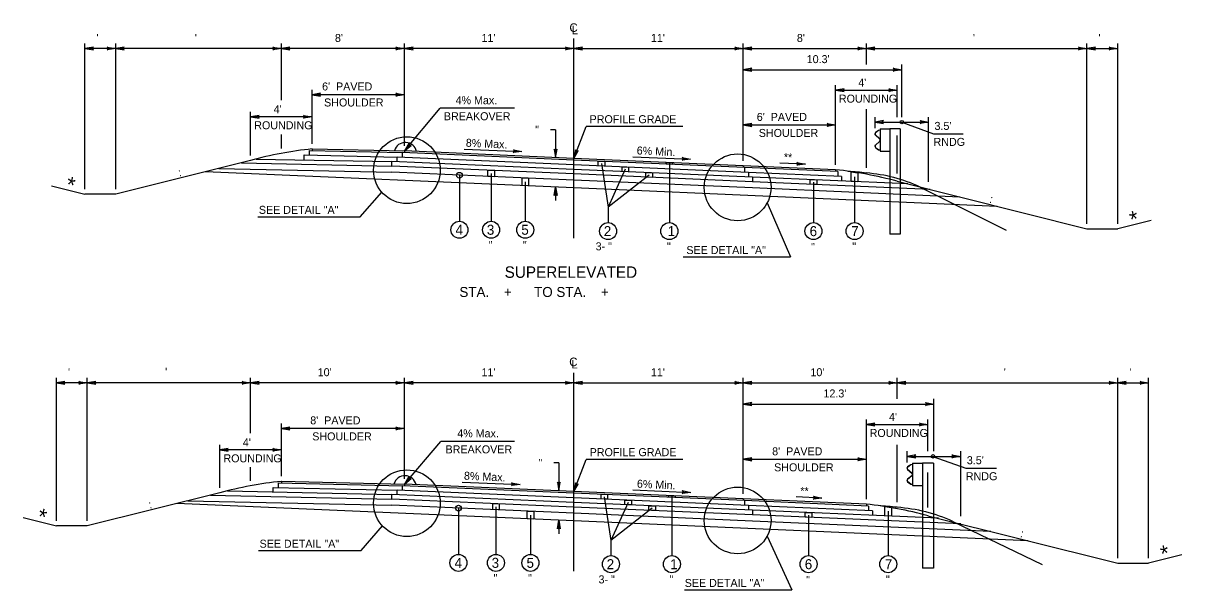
# Model space of a CAD drawing. Extents: x -592 to 1199, y -590 to 416.
# Drawn here: x 716.2 to 918.9, y -324.2 to -225.1 of the extents above; entities that cross this region are included whole.
import ezdxf

# ---------------------------------------------------------------- set-up
doc = ezdxf.new("R2010")
doc.units = 0
doc.layers.add('1', color=7, linetype='Continuous')
doc.layers.add('Des_ Drain_ Ftrs', color=7, linetype='Continuous')

msp = doc.modelspace()

# ---------------------------------------------------------------- linework, layer by layer
at = {"layer": '1'}
for p, q in [((726.98, -254.1), (726.98, -228.63)), ((732.37, -254.1), (732.37, -228.63)), ((761.34, -238.52), (761.34, -228.63)), ((782.89, -246.54), (782.89, -228.63)), ((812.53, -262.69), (812.53, -227.75)), ((842.16, -249.13), (842.16, -228.63)), ((863.71, -232.33), (863.71, -228.63)), ((902.31, -260.15), (902.31, -228.63)), ((907.69, -260.15), (907.69, -228.63)), ((732.37, -229.51), (726.98, -229.51)), ((761.34, -229.51), (732.37, -229.51)), ((782.89, -229.51), (761.34, -229.51)), ((812.53, -229.51), (782.89, -229.51)), ((812.53, -229.51), (842.16, -229.51)), ((842.16, -229.51), (863.71, -229.51)), ((863.71, -229.51), (902.31, -229.51)), ((902.31, -229.51), (907.69, -229.51)), ((869.91, -241.49), (869.91, -232.33)), ((842.16, -233.21), (869.91, -233.21)), ((766.73, -246.19), (766.73, -236.71)), ((858.33, -249.84), (858.33, -235.9)), ((858.33, -236.78), (869.1, -236.78)), ((869.1, -241.49), (869.1, -235.9)), ((782.89, -237.59), (766.73, -237.59)), ((755.95, -248.2), (755.95, -240.57)), ((782.88, -247.42), (789.14, -239.95)), ((802.11, -239.95), (789.14, -239.95)), ((863.71, -250.4), (863.71, -240.14)), ((766.73, -241.45), (755.95, -241.45)), ((812.53, -248.72), (814.67, -243.15)), ((831.59, -243.15), (814.67, -243.15)), ((842.16, -242.87), (858.33, -242.87)), ((865.22, -243.44), (865.22, -241.49)), ((865.22, -242.37), (874.6, -242.37)), ((869.91, -242.37), (875.47, -244.44)), ((874.6, -252.85), (874.6, -241.49)), ((761.34, -246.97), (761.34, -244.52)), ((809.33, -243.7), (808.45, -243.7)), ((809.33, -243.7), (809.33, -248.58)), ((865.28, -244.66), (866.01, -245.29)), ((865.82, -243.83), (865.3, -244.22)), ((865.3, -244.63), (866.03, -245.27)), ((865.83, -243.86), (865.32, -244.25)), ((866.13, -243.78), (865.82, -243.83)), ((866.13, -243.81), (865.83, -243.86)), ((866.13, -243.55), (866.13, -247.48)), ((866.13, -243.55), (867.82, -243.55)), ((867.82, -243.55), (867.82, -261.95)), ((869.64, -243.55), (867.82, -243.55)), ((869.1, -251.36), (869.1, -244.72)), ((869.64, -243.55), (869.64, -261.95)), ((875.47, -244.44), (880.62, -244.44)), ((766.73, -247.07), (782.88, -247.42)), ((766.73, -247.07), (766.73, -247.37)), ((793.31, -247.08), (803.42, -247.52)), ((866.01, -245.74), (865.28, -246.38)), ((866.03, -245.76), (865.3, -246.4)), ((865.3, -246.81), (865.82, -247.2)), ((865.32, -246.79), (865.83, -247.17)), ((865.82, -247.2), (866.13, -247.25)), ((865.83, -247.17), (866.13, -247.22)), ((866.1, -245.48), (866.1, -245.55)), ((866.13, -245.48), (866.13, -245.55)), ((755.95, -249.08), (732.37, -254.98)), ((756.91, -248.83), (780.7, -249.25)), ((765.34, -248.12), (781.62, -248.48)), ((765.34, -248.98), (765.34, -248.12)), ((766.27, -247.36), (782.54, -247.71)), ((766.27, -248.14), (766.27, -247.36)), ((812.53, -250.64), (780.7, -249.25)), ((780.7, -250.06), (780.7, -249.25)), ((812.53, -249.83), (781.62, -248.48)), ((781.62, -249.29), (781.62, -248.48)), ((812.53, -249.02), (782.54, -247.71)), ((782.54, -248.52), (782.54, -247.71)), ((812.53, -248.72), (782.88, -247.42)), ((782.88, -247.42), (782.88, -247.72)), ((842.17, -250.01), (812.53, -248.72)), ((842.4, -250.32), (812.53, -249.02)), ((822.83, -248.42), (832.94, -248.86)), ((866.13, -247.48), (867.82, -247.48)), ((812.53, -253.87), (748.05, -251.06)), ((750.39, -250.47), (780.7, -251.14)), ((754.35, -249.48), (780.7, -250.06)), ((812.53, -251.45), (780.7, -250.06)), ((812.53, -252.52), (780.7, -251.14)), ((798.05, -251.38), (798.05, -259.72)), ((843.1, -251.16), (812.53, -249.83)), ((843.81, -252), (812.53, -250.64)), ((817.35, -249.63), (818.51, -257.26)), ((821.52, -250.62), (818.51, -257.26)), ((829.23, -249.62), (829.23, -259.96)), ((858.33, -250.72), (842.17, -250.01)), ((842.17, -250.01), (842.17, -250.31)), ((858.69, -251.03), (842.4, -250.32)), ((842.4, -250.32), (842.4, -251.13)), ((859.38, -251.87), (843.1, -251.16)), ((843.1, -251.16), (843.1, -251.97)), ((853.03, -249.74), (848.54, -249.55)), ((858.33, -250.72), (858.33, -251.02)), ((858.69, -251.03), (858.69, -251.84)), ((792.5, -251.67), (792.5, -259.72)), ((804.02, -252.8), (804.02, -259.72)), ((843.81, -252.81), (812.53, -251.45)), ((843.81, -253.89), (812.53, -252.52)), ((825.7, -251.63), (818.51, -257.26)), ((843.81, -252), (843.81, -252.81)), ((870.94, -253.19), (843.81, -252)), ((874.86, -254.17), (843.81, -252.81)), ((854.45, -252.89), (854.45, -259.96)), ((859.38, -251.87), (859.38, -252.68)), ((861.65, -251.94), (861.65, -259.96)), ((865.22, -251.5), (865.22, -251.5)), ((869.1, -252.73), (902.3, -261.03)), ((721.15, -253.52), (726.98, -254.98)), ((732.37, -254.98), (726.98, -254.98)), ((775.16, -258.92), (778.9, -254.6)), ((809.33, -253.73), (809.33, -256.1)), ((886.62, -257.11), (812.53, -253.87)), ((880.08, -255.48), (843.81, -253.89)), ((873.1, -253.73), (888.15, -261.26)), ((818.51, -257.26), (818.51, -259.96)), ((846.36, -256.49), (850.42, -265.95)), ((757.22, -258.92), (775.16, -258.92)), ((902.3, -261.03), (907.69, -261.03)), ((913.52, -259.57), (907.69, -261.03)), ((869.64, -261.95), (867.82, -261.95)), ((831.63, -265.95), (850.42, -265.95)), ((721.99, -312.13), (721.99, -287.1)), ((727.38, -312.13), (727.38, -287.1)), ((755.95, -296.8), (755.95, -287.1)), ((782.89, -304.79), (782.89, -287.1)), ((812.53, -320.94), (812.53, -286.22)), ((842.16, -307.38), (842.16, -287.1)), ((869.1, -290.8), (869.1, -287.1)), ((907.69, -318.63), (907.69, -287.1)), ((913.08, -318.63), (913.08, -287.1)), ((727.38, -287.98), (721.99, -287.98)), ((755.95, -287.98), (727.38, -287.98)), ((782.89, -287.98), (755.95, -287.98)), ((812.53, -287.98), (782.89, -287.98)), ((812.53, -287.98), (842.16, -287.98)), ((842.16, -287.98), (869.1, -287.98)), ((869.1, -287.98), (907.69, -287.98)), ((907.69, -287.98), (913.08, -287.98)), ((842.16, -291.68), (875.53, -291.68)), ((875.53, -299.95), (875.53, -290.8)), ((761.34, -304.32), (761.34, -295.06)), ((782.89, -295.94), (761.34, -295.94)), ((863.71, -308.32), (863.71, -294.37)), ((863.71, -295.25), (874.49, -295.25)), ((874.49, -299.95), (874.49, -294.37)), ((750.56, -306.33), (750.56, -298.81)), ((761.34, -299.69), (750.56, -299.69)), ((782.88, -305.67), (789.22, -298.21)), ((802.15, -298.21), (789.22, -298.21)), ((869.1, -308.86), (869.1, -298.82)), ((870.84, -301.9), (870.84, -299.95)), ((880.22, -311.32), (880.22, -299.95)), ((809.9, -301.97), (809.02, -301.97)), ((809.9, -301.97), (809.9, -306.85)), ((812.53, -306.97), (814.68, -301.38)), ((831.6, -301.38), (814.68, -301.38)), ((842.16, -301.35), (863.71, -301.35)), ((870.84, -300.83), (880.22, -300.83)), ((871.79, -302.02), (871.79, -305.95)), ((871.79, -302.02), (873.53, -302.02)), ((873.53, -302.02), (873.53, -320.41)), ((875.43, -302.02), (873.53, -302.02)), ((875.36, -300.83), (881.12, -302.91)), ((875.43, -302.02), (875.43, -320.41)), ((755.95, -305.1), (755.95, -302.75)), ((870.91, -303.12), (871.67, -303.76)), ((871.46, -302.3), (870.92, -302.69)), ((870.93, -303.1), (871.69, -303.74)), ((871.47, -302.33), (870.94, -302.71)), ((871.79, -302.25), (871.46, -302.3)), ((871.79, -302.28), (871.47, -302.33)), ((871.76, -303.95), (871.76, -304.02)), ((871.79, -303.95), (871.79, -304.02)), ((874.49, -309.78), (874.49, -303.63)), ((881.12, -302.91), (886.47, -302.91)), ((760.85, -305.49), (782.54, -305.96)), ((760.85, -306.27), (760.85, -305.49)), ((761.34, -305.2), (782.88, -305.67)), ((761.34, -305.2), (761.34, -305.5)), ((812.53, -307.27), (782.54, -305.96)), ((782.54, -306.77), (782.54, -305.96)), ((812.53, -306.97), (782.88, -305.67)), ((782.88, -305.67), (782.88, -305.97)), ((792.99, -305.32), (803.1, -305.76)), ((871.67, -304.21), (870.91, -304.84)), ((870.92, -305.28), (871.46, -305.67)), ((871.69, -304.23), (870.93, -304.87)), ((870.94, -305.25), (871.47, -305.64)), ((871.46, -305.67), (871.79, -305.72)), ((871.47, -305.64), (871.79, -305.69)), ((871.79, -305.95), (873.53, -305.95)), ((750.56, -307.21), (727.38, -313.01)), ((748.97, -307.61), (780.7, -308.31)), ((751.89, -306.87), (780.7, -307.5)), ((759.92, -306.25), (781.62, -306.73)), ((759.92, -307.04), (759.92, -306.25)), ((812.53, -308.89), (780.7, -307.5)), ((780.7, -308.31), (780.7, -307.5)), ((812.53, -308.08), (781.62, -306.73)), ((781.62, -307.54), (781.62, -306.73)), ((842.17, -308.26), (812.53, -306.97)), ((842.4, -308.57), (812.53, -307.27)), ((843.1, -309.41), (812.53, -308.08)), ((817.85, -307.9), (819.02, -315.52)), ((822.86, -306.7), (832.98, -307.14)), ((829.68, -307.88), (829.68, -318.21)), ((855.92, -308.12), (851.43, -307.92)), ((812.53, -312.12), (743.06, -309.09)), ((745, -308.6), (780.7, -309.38)), ((812.53, -309.69), (780.7, -308.31)), ((812.53, -310.77), (780.7, -309.38)), ((792.33, -309.89), (792.33, -317.97)), ((798.89, -309.64), (798.89, -317.97)), ((843.81, -310.25), (812.53, -308.89)), ((843.81, -311.06), (812.53, -309.69)), ((822.03, -308.88), (819.02, -315.52)), ((826.2, -309.89), (819.02, -315.52)), ((863.71, -309.2), (842.17, -308.26)), ((842.17, -308.26), (842.17, -308.56)), ((864.1, -309.52), (842.4, -308.57)), ((842.4, -308.57), (842.4, -309.38)), ((864.8, -310.36), (843.1, -309.41)), ((843.1, -309.41), (843.1, -310.22)), ((863.71, -309.2), (863.71, -309.5)), ((864.1, -309.52), (864.1, -310.33)), ((870.84, -309.96), (870.84, -309.96)), ((716.16, -311.55), (721.99, -313.01)), ((804.93, -311.11), (804.93, -317.97)), ((809.9, -312), (809.9, -314.37)), ((843.81, -312.14), (812.53, -310.77)), ((892.01, -315.59), (812.53, -312.12)), ((843.81, -310.25), (843.81, -311.06)), ((876.32, -311.67), (843.81, -310.25)), ((880.24, -312.65), (843.81, -311.06)), ((885.47, -313.96), (843.81, -312.14)), ((853.6, -311.1), (853.6, -318.21)), ((864.8, -310.36), (864.8, -311.17)), ((867.53, -310.42), (867.53, -318.21)), ((874.49, -311.21), (907.69, -319.51)), ((878.84, -312.2), (894.46, -319.72)), ((727.38, -313.01), (721.99, -313.01)), ((775.28, -317.31), (779.02, -312.99)), ((819.02, -315.52), (819.02, -318.21)), ((846.34, -314.78), (850.69, -324.17)), ((757.35, -317.31), (775.28, -317.31)), ((918.9, -318.06), (913.08, -319.51)), ((907.69, -319.51), (913.08, -319.51)), ((875.43, -320.41), (873.53, -320.41)), ((831.91, -324.17), (850.69, -324.17))]:
    msp.add_line(p, q, dxfattribs=at)
for points in [[(816.77, -249.2), (817.92, -249.25), (817.92, -250.06), (816.77, -250.01)], [(797.48, -250.79), (798.63, -250.84), (798.63, -251.92), (797.48, -251.87)], [(820.95, -250.2), (822.1, -250.25), (822.1, -251.06), (820.95, -251.01)], [(825.12, -251.19), (826.27, -251.24), (826.27, -252.05), (825.12, -252)], [(828.66, -249.42), (829.8, -249.47), (829.8, -249.77), (828.66, -249.72)], [(861.07, -251.06), (862.22, -251.24), (862.22, -252.81), (861.07, -252.76)], [(803.45, -252.13), (804.6, -252.18), (804.6, -253.53), (803.45, -253.48)], [(853.88, -252.44), (855.02, -252.49), (855.02, -253.3), (853.88, -253.25)], [(817.28, -307.47), (818.43, -307.52), (818.43, -308.33), (817.28, -308.28)], [(829.1, -307.69), (830.25, -307.74), (830.25, -308.04), (829.1, -307.99)], [(798.32, -309.07), (799.47, -309.12), (799.47, -310.2), (798.32, -310.15)], [(821.45, -308.47), (822.6, -308.52), (822.6, -309.33), (821.45, -309.28)], [(825.63, -309.46), (826.78, -309.51), (826.78, -310.32), (825.63, -310.27)], [(866.96, -309.62), (868.11, -309.8), (868.11, -311.31), (866.96, -311.26)], [(804.36, -310.42), (805.5, -310.47), (805.5, -311.81), (804.36, -311.76)], [(853.02, -310.65), (854.17, -310.7), (854.17, -311.51), (853.02, -311.46)]]:
    msp.add_lwpolyline(points, close=True, dxfattribs=at)
for centre, radius in [((869.91, -242.37), 0.3), ((783.31, -250.78), 5.84), ((841.18, -253.79), 5.84), ((792.5, -251.67), 0.5), ((792.5, -261.21), 1.49), ((798.05, -261.21), 1.49), ((804.02, -261.21), 1.49), ((818.51, -261.44), 1.49), ((829.23, -261.44), 1.49), ((854.45, -261.44), 1.49), ((861.65, -261.44), 1.49), ((783.31, -309.03), 5.84), ((841.18, -312.04), 5.84), ((792.33, -309.89), 0.5), ((792.33, -319.46), 1.49), ((798.89, -319.46), 1.49), ((804.93, -319.46), 1.49), ((819.02, -319.69), 1.49), ((829.68, -319.69), 1.49), ((853.6, -319.69), 1.49), ((867.53, -319.69), 1.49)]:
    msp.add_circle(centre, radius, dxfattribs=at)
for centre, radius, start, end in [((865.47, -244.45), 0.278, 126.9799, 229.021), ((865.47, -244.45), 0.249, 126.9799, 229.021), ((865.85, -245.48), 0.249, 0, 49.0365), ((865.85, -245.48), 0.278, 0, 49.0365), ((773.62, -313.9), 67.19, 95.8897, 105.2483), ((783.04, -247.94), 2, 12.248, 163.8505), ((865.47, -246.59), 0.278, 130.979, 233.0201), ((865.47, -246.59), 0.249, 130.979, 233.0201), ((865.85, -245.55), 0.249, 310.9635, 0), ((865.85, -245.55), 0.278, 310.9635, 0), ((851.44, -317.55), 67.19, 74.7602, 84.1188), ((852.89, -351.94), 101.24, 83.8633, 85.6775), ((861.59, -278.56), 27.37, 65.1374, 85.5513), ((768.23, -372.04), 67.19, 95.8911, 105.2497), ((782.96, -306.21), 2, 12.9578, 163.1849), ((856.83, -376.04), 67.19, 74.7602, 84.1188)]:
    msp.add_arc(centre, radius, start, end, dxfattribs=at)
msp.add_ellipse((875.36, -300.83), major_axis=(-0.311, 0), ratio=0.964041, dxfattribs=at)
for centre, major_axis, start_param, end_param in [((871.1, -302.91), (-0.288, 0), 5.35781, 7.138763), ((871.1, -302.91), (-0.258, 0), 5.35781, 7.138763), ((871.5, -303.95), (0.258, 0), 0, 0.855848), ((871.5, -304.02), (0.258, 0), 5.427337, 6.283185), ((871.5, -303.95), (0.288, 0), 0, 0.855848), ((871.5, -304.02), (0.288, 0), 5.427337, 6.283185), ((871.1, -305.05), (-0.288, 0), 5.427608, 7.208561), ((871.1, -305.05), (-0.258, 0), 5.427608, 7.208561), ((857.88, -410.41), (105.02, 0), 1.463691, 1.495354), ((866.91, -337.03), (28.39, 0), 1.136862, 1.493152)]:
    msp.add_ellipse(centre, major_axis=major_axis, ratio=0.964041, start_param=start_param, end_param=end_param, dxfattribs=at)
at = {"layer": 'Des_ Drain_ Ftrs'}
for points in [[(726.98, -229.51), (728.47, -229.76), (728.17, -229.51), (728.47, -229.26)], [(732.37, -229.51), (730.88, -229.76), (731.17, -229.51), (730.88, -229.26)], [(732.37, -229.51), (733.86, -229.76), (733.56, -229.51), (733.86, -229.26)], [(761.34, -229.51), (759.85, -229.76), (760.14, -229.51), (759.85, -229.26)], [(761.34, -229.51), (762.83, -229.76), (762.53, -229.51), (762.83, -229.26)], [(782.89, -229.51), (781.4, -229.76), (781.7, -229.51), (781.4, -229.26)], [(782.89, -229.51), (784.38, -229.76), (784.08, -229.51), (784.38, -229.26)], [(812.53, -229.51), (811.04, -229.76), (811.33, -229.51), (811.04, -229.26)], [(812.53, -229.51), (814.01, -229.76), (813.72, -229.51), (814.01, -229.26)], [(842.16, -229.51), (840.67, -229.76), (840.97, -229.51), (840.67, -229.26)], [(842.16, -229.51), (843.65, -229.76), (843.35, -229.51), (843.65, -229.26)], [(863.71, -229.51), (862.23, -229.76), (862.52, -229.51), (862.23, -229.26)], [(863.71, -229.51), (865.2, -229.76), (864.91, -229.51), (865.2, -229.26)], [(902.31, -229.51), (900.82, -229.76), (901.11, -229.51), (900.82, -229.26)], [(902.31, -229.51), (903.79, -229.76), (903.5, -229.51), (903.79, -229.26)], [(907.69, -229.51), (906.21, -229.76), (906.5, -229.51), (906.21, -229.26)], [(842.16, -233.21), (843.65, -233.46), (843.35, -233.21), (843.65, -232.96)], [(869.91, -233.21), (868.42, -233.46), (868.72, -233.21), (868.42, -232.96)], [(858.33, -236.78), (859.81, -237.03), (859.52, -236.78), (859.81, -236.54)], [(869.1, -236.78), (867.61, -237.03), (867.91, -236.78), (867.61, -236.54)], [(766.73, -237.59), (768.21, -237.83), (767.92, -237.59), (768.21, -237.34)], [(782.89, -237.59), (781.4, -237.83), (781.7, -237.59), (781.4, -237.34)], [(755.95, -241.45), (757.44, -241.7), (757.14, -241.45), (757.44, -241.2)], [(766.73, -241.45), (765.24, -241.7), (765.53, -241.45), (765.24, -241.2)], [(842.16, -242.87), (843.65, -243.12), (843.35, -242.87), (843.65, -242.62)], [(858.33, -242.87), (856.84, -243.12), (857.13, -242.87), (856.84, -242.62)], [(865.22, -242.37), (866.71, -242.61), (866.41, -242.37), (866.71, -242.12)], [(874.6, -242.37), (873.11, -242.61), (873.41, -242.37), (873.11, -242.12)], [(782.88, -247.42), (784.03, -246.44), (783.65, -246.51), (783.65, -246.12)], [(803.42, -247.52), (801.92, -247.71), (802.23, -247.47), (801.95, -247.21)], [(809.33, -248.58), (809.58, -247.09), (809.33, -247.39), (809.08, -247.09)], [(812.53, -248.72), (813.29, -247.42), (812.95, -247.6), (812.83, -247.24)], [(832.94, -248.86), (831.45, -249.05), (831.75, -248.81), (831.47, -248.55)], [(853.03, -249.74), (851.54, -249.93), (851.84, -249.69), (851.56, -249.43)], [(809.33, -253.73), (809.58, -255.22), (809.33, -254.93), (809.08, -255.22)], [(721.99, -287.98), (723.48, -288.22), (723.19, -287.98), (723.48, -287.73)], [(727.38, -287.98), (725.89, -288.22), (726.19, -287.98), (725.89, -287.73)], [(727.38, -287.98), (728.87, -288.22), (728.57, -287.98), (728.87, -287.73)], [(755.95, -287.98), (754.46, -288.22), (754.76, -287.98), (754.46, -287.73)], [(755.95, -287.98), (757.44, -288.22), (757.14, -287.98), (757.44, -287.73)], [(782.89, -287.98), (781.4, -288.22), (781.7, -287.98), (781.4, -287.73)], [(782.89, -287.98), (784.38, -288.22), (784.08, -287.98), (784.38, -287.73)], [(812.53, -287.98), (811.04, -288.22), (811.33, -287.98), (811.04, -287.73)], [(812.53, -287.98), (814.01, -288.22), (813.72, -287.98), (814.01, -287.73)], [(842.16, -287.98), (840.67, -288.22), (840.97, -287.98), (840.67, -287.73)], [(842.16, -287.98), (843.65, -288.22), (843.35, -287.98), (843.65, -287.73)], [(869.1, -287.98), (867.61, -288.22), (867.91, -287.98), (867.61, -287.73)], [(869.1, -287.98), (870.59, -288.22), (870.3, -287.98), (870.59, -287.73)], [(907.69, -287.98), (906.2, -288.22), (906.5, -287.98), (906.2, -287.73)], [(907.69, -287.98), (909.18, -288.22), (908.88, -287.98), (909.18, -287.73)], [(913.08, -287.98), (911.59, -288.22), (911.88, -287.98), (911.59, -287.73)], [(842.16, -291.68), (843.65, -291.93), (843.36, -291.68), (843.65, -291.43)], [(875.53, -291.68), (874.04, -291.93), (874.34, -291.68), (874.04, -291.43)], [(761.34, -295.94), (762.83, -296.19), (762.53, -295.94), (762.83, -295.7)], [(782.89, -295.94), (781.4, -296.19), (781.7, -295.94), (781.4, -295.7)], [(863.71, -295.25), (865.2, -295.5), (864.91, -295.25), (865.2, -295)], [(874.49, -295.25), (873, -295.5), (873.3, -295.25), (873, -295)], [(750.56, -299.69), (752.05, -299.94), (751.75, -299.69), (752.05, -299.44)], [(761.34, -299.69), (759.85, -299.94), (760.14, -299.69), (759.85, -299.44)], [(842.16, -301.35), (843.65, -301.6), (843.35, -301.35), (843.65, -301.1)], [(863.71, -301.35), (862.23, -301.6), (862.52, -301.35), (862.23, -301.1)], [(870.84, -300.83), (872.38, -301.08), (872.08, -300.83), (872.38, -300.59)], [(880.22, -300.83), (878.68, -301.08), (878.99, -300.83), (878.68, -300.59)], [(782.88, -305.67), (784.04, -304.7), (783.66, -304.76), (783.66, -304.38)], [(803.1, -305.76), (801.6, -305.94), (801.91, -305.71), (801.63, -305.45)], [(809.9, -306.85), (810.15, -305.36), (809.9, -305.66), (809.65, -305.36)], [(812.53, -306.97), (813.29, -305.67), (812.95, -305.85), (812.83, -305.49)], [(832.98, -307.14), (831.48, -307.33), (831.79, -307.09), (831.5, -306.83)], [(855.92, -308.12), (854.42, -308.3), (854.73, -308.07), (854.45, -307.8)], [(809.9, -312), (810.15, -313.49), (809.9, -313.2), (809.65, -313.49)]]:
    msp.add_lwpolyline(points, close=True, dxfattribs=at)

# ---------------------------------------------------------------- texts
at = {"layer": '1'}
for s, height, p in [(" '", 1.4, (728.48, -228.36)), ("  '", 1.4, (745.16, -228.36)), ("8'", 1.4, (770.72, -228.36)), ("11'", 1.4, (796.36, -228.36)), ("11'", 1.4, (826, -228.36)), ("8'", 1.4, (851.55, -228.36)), ("  '", 1.4, (881.31, -228.36)), (" '", 1.4, (903.8, -228.36)), ("10.3'", 1.4, (853.27, -232.06)), ("4'", 1.4, (862.29, -236.17)), ("6'  PAVED", 1.4, (768.47, -236.84)), ('SHOULDER', 1.4, (768.82, -239.64)), ('4% Max.', 1.4, (791.83, -239.25)), ('ROUNDING', 1.4, (858.9, -238.97)), ("4'", 1.4, (759.99, -240.83)), ('BREAKOVER', 1.4, (789.78, -242.05)), ('PROFILE GRADE', 1.4, (815.28, -242.57)), ("6'  PAVED", 1.4, (844.53, -242.17)), ('ROUNDING', 1.4, (756.6, -243.63)), ("3.5'", 1.4, (875.63, -243.74)), ('SHOULDER', 1.4, (844.88, -244.97)), ('RNDG', 1.4, (875.46, -246.54)), ('SEE DETAIL "A"', 1.4, (757.41, -258.42)), ('4', 1.75, (791.82, -262.08)), ('3', 1.75, (797.3, -262.08)), ('5', 1.75, (803.33, -262.08)), ('2', 1.75, (817.76, -262.32)), ('1', 1.75, (828.93, -262.32)), ('6', 1.75, (853.78, -262.32)), ('7', 1.75, (861.06, -262.32)), (' "', 1.4, (797.11, -264.57)), (' "', 1.4, (803.08, -264.57)), ('3- "', 1.4, (816.33, -264.8)), (' "', 1.4, (828.29, -264.8)), (' "', 1.4, (853.51, -264.9)), ('  "', 1.4, (860.2, -264.8)), ('SEE DETAIL "A"', 1.4, (832.21, -265.45)), ('SUPERELEVATED', 2, (800.41, -269.61)), ('STA.    +      TO STA.    +     ', 1.75, (792.5, -272.96)), (" '", 1.4, (723.49, -286.82)), ("  '", 1.4, (739.97, -286.75)), ("10'", 1.4, (767.7, -286.82)), ("11'", 1.4, (796.36, -286.82)), ("11'", 1.4, (826, -286.82)), ("10'", 1.4, (853.92, -286.82)), ("  '", 1.4, (886.7, -286.82)), (" '", 1.4, (909.19, -286.82)), ("12.3'", 1.4, (856.2, -290.53)), ("8'  PAVED", 1.4, (766.4, -295.24)), ("4'", 1.4, (867.67, -294.64)), ("4'", 1.4, (754.6, -299.08)), ('SHOULDER', 1.4, (766.75, -298.04)), ('4% Max.', 1.4, (792.12, -297.51)), ('ROUNDING', 1.4, (864.28, -297.44)), ('BREAKOVER', 1.4, (790.07, -300.31)), ('PROFILE GRADE', 1.4, (815.29, -300.8)), ("8'  PAVED", 1.4, (847.22, -300.65)), ('ROUNDING', 1.4, (751.21, -301.88)), ('SHOULDER', 1.4, (847.57, -303.45)), ("3.5'", 1.4, (881.29, -302.21)), ('RNDG', 1.4, (881.11, -305.01)), ('SEE DETAIL "A"', 1.4, (757.53, -316.81)), ('4', 1.75, (791.66, -320.33)), ('3', 1.75, (798.14, -320.33)), ('5', 1.75, (804.24, -320.33)), ('2', 1.75, (818.27, -320.57)), ('1', 1.75, (829.38, -320.57)), ('6', 1.75, (852.93, -320.57)), ('7', 1.75, (866.94, -320.57)), (' "', 1.4, (797.95, -322.82)), (' "', 1.4, (803.99, -322.82)), ('3- "', 1.4, (816.84, -323.05)), (' "', 1.4, (828.73, -323.05)), ('SEE DETAIL "A"', 1.4, (831.92, -323.67)), (' "', 1.4, (852.65, -323.15)), ('  "', 1.4, (866.09, -323.05))]:
    msp.add_text(s, height=height, dxfattribs=at).set_placement(p)
for s, height, rotation, p in [('  "', 1.4, 0.1438, (804.72, -244.4)), ('8% Max.', 1.4, 357.3761, (793.59, -246.67)), ('6% Min.', 1.4, 357.3732, (823.5, -248.02)), ('**', 1.4, 357.216, (849.22, -249.18)), (' : ', 1.4, 14.2282, (742.98, -252.04)), ('*', 2.8, 347.1521, (723.46, -254.55)), (' : ', 1.4, 345.7718, (884.65, -256.33)), ('*', 2.8, 12.8479, (910.15, -260.84)), ('  "', 1.4, 0.1438, (805.29, -302.68)), ('8% Max.', 1.4, 357.3762, (793.27, -304.9)), ('6% Min.', 1.4, 357.376, (823.53, -306.3)), ('**', 1.4, 357.2166, (852.11, -307.56)), ('*', 2.8, 347.1521, (718.48, -312.58)), (' : ', 1.4, 14.2282, (737.79, -310.12)), (' : ', 1.4, 345.7718, (890.04, -314.81)), ('*', 2.8, 12.8479, (915.54, -319.32))]:
    msp.add_text(s, height=height, rotation=rotation, dxfattribs=at).set_placement(p)
at = {"layer": 'Des_ Drain_ Ftrs'}
for s, p in [('C', (811.75, -226.6)), ('L', (812.14, -227)), ('C', (811.71, -285.06)), ('L', (812.1, -285.46))]:
    msp.add_text(s, height=1.5, dxfattribs=at).set_placement(p)

doc.saveas('drawing.dxf')
